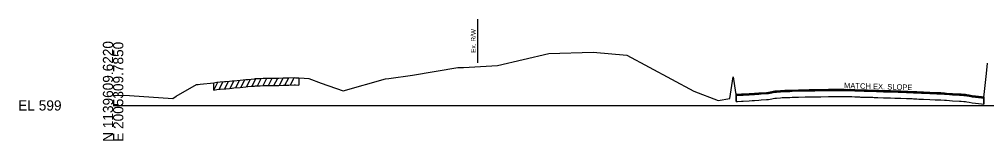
# Model space of a CAD drawing. Extents: x -201 to 2007062, y -213 to 1139737.
# Drawn here: x -25.7 to 239.3, y 490.3 to 523.7 of the extents above; entities that cross this region are included whole.
import ezdxf

# ---------------------------------------------------------------- set-up
doc = ezdxf.new("R2010")
doc.units = 0
for name, color, linetype in [('Default', 7, 'Continuous'), ('RD_GPK_XS_Cell', 7, 'Continuous'), ('RD_XS_ExGround', 7, 'Continuous'), ('RD_XS_ExPaveRet', 7, 'Continuous'), ('RD_XS_ExRW', 7, 'Continuous'), ('RD_XS_PaveOvlay', 7, 'Continuous'), ('RD_XS_TX_Slope', 7, 'Continuous')]:
    doc.layers.add(name, color=color, linetype=linetype)

msp = doc.modelspace()

# ---------------------------------------------------------------- linework, layer by layer
at = {"layer": 'RD_GPK_XS_Cell'}
msp.add_line((0, 500), (250, 500), dxfattribs=at)
at = {"layer": 'RD_XS_ExGround'}
msp.add_lwpolyline([(0, 502.8), (4.53, 502.75), (16.32, 501.89), (17.31, 502.56), (22.87, 505.74), (23.31, 505.78), (23.84, 505.83), (27.58, 506.23), (28.41, 506.37), (29.31, 506.45), (30.53, 506.57), (30.88, 506.6), (31.85, 506.69), (32.65, 506.76), (33.1, 506.8), (34.78, 506.95), (36.38, 507.11), (36.9, 507.16), (37.85, 507.25), (38.71, 507.33), (39.02, 507.36), (40.28, 507.41), (41.14, 507.45), (41.85, 507.46), (43.41, 507.47), (43.84, 507.48), (44.98, 507.51), (45.38, 507.52), (46.55, 507.55), (47.5, 507.57), (48.11, 507.59), (49.63, 507.64), (50, 507.62), (50.92, 507.61), (52.33, 507.52), (53.65, 507.39), (57.01, 506.14), (63.05, 503.99), (74.59, 507.28), (75.51, 507.42), (82.01, 508.34), (94.48, 510.4), (95.96, 510.44), (105.32, 510.97), (119.35, 514.25), (131.53, 514.68), (140.71, 513.81), (159.13, 503.88), (165.76, 501.33), (169, 501.89), (169.92, 507.82), (170.55, 503.57), (170.75, 503.12), (171.06, 503.11), (172.19, 503.15), (172.67, 503.16), (174.26, 503.26), (175.05, 503.31), (175.77, 503.37), (176.91, 503.48), (177.54, 503.5), (179.04, 503.59), (179.57, 503.64), (180.04, 503.75), (181.32, 503.98), (181.77, 504.02), (182.88, 504.11), (183.36, 504.14), (184.04, 504.18), (185.4, 504.2), (186.02, 504.23), (187.77, 504.3), (189.64, 504.33), (190.67, 504.34), (191.76, 504.35), (192.29, 504.36), (193.89, 504.4), (196.01, 504.45), (196.37, 504.47), (196.9, 504.47), (197.47, 504.47), (198.13, 504.47), (198.55, 504.46), (199.76, 504.45), (200.25, 504.44), (201.69, 504.42), (202.37, 504.41), (203.26, 504.39), (204.49, 504.32), (204.82, 504.31), (205.76, 504.28), (206.61, 504.26), (207.39, 504.24), (208.14, 504.23), (208.51, 504.21), (209.19, 504.18), (209.52, 504.17), (211.09, 504.11), (211.75, 504.1), (212.98, 504.08), (214.23, 504.04), (215.1, 504), (215.79, 503.97), (217.36, 503.91), (217.75, 503.9), (218.93, 503.86), (219.34, 503.83), (220.22, 503.79), (220.73, 503.76), (221.47, 503.74), (222.06, 503.71), (223.75, 503.65), (225.2, 503.58), (225.71, 503.56), (226.76, 503.51), (227.83, 503.45), (228.33, 503.41), (229.95, 503.28), (231.86, 503.17), (232.34, 503.15), (233.09, 503.1), (233.52, 503.07), (233.95, 503), (234.52, 502.88), (235.33, 502.71), (236.31, 502.61), (237.13, 502.51), (237.97, 502.43), (238.54, 502.39), (238.64, 503.03), (239.29, 508.81), (239.59, 511.58)], dxfattribs=at)
at = {"layer": 'RD_XS_ExPaveRet'}
for p, q in [((27.58, 504.23), (28.66, 506.39)), ((27.58, 504.23), (27.58, 506.23)), ((29.08, 504.43), (30.13, 506.53)), ((30.58, 504.57), (31.63, 506.67)), ((32.08, 504.71), (33.13, 506.81)), ((33.58, 504.85), (34.63, 506.94)), ((35.08, 504.98), (36.13, 507.08)), ((36.58, 505.13), (37.63, 507.23)), ((38.08, 505.27), (39.13, 507.36)), ((39.58, 505.38), (40.6, 507.42)), ((41.08, 505.44), (42.09, 507.46)), ((42.58, 505.47), (43.59, 507.48)), ((44.08, 505.49), (45.09, 507.51)), ((45.58, 505.52), (46.59, 507.55)), ((47.08, 505.56), (48.1, 507.59)), ((48.58, 505.61), (49.6, 507.64)), ((50.92, 507.61), (50.92, 505.61)), ((27.58, 504.23), (28.41, 504.37)), ((28.41, 504.37), (29.31, 504.45)), ((29.31, 504.45), (30.53, 504.57)), ((30.53, 504.57), (30.88, 504.6)), ((30.88, 504.6), (31.85, 504.69)), ((31.85, 504.69), (32.65, 504.76)), ((32.65, 504.76), (33.1, 504.8)), ((33.1, 504.8), (34.78, 504.95)), ((34.78, 504.95), (36.38, 505.11)), ((36.38, 505.11), (36.9, 505.16)), ((36.9, 505.16), (37.85, 505.25)), ((37.85, 505.25), (38.71, 505.33)), ((38.71, 505.33), (39.02, 505.36)), ((39.02, 505.36), (40.28, 505.41)), ((40.28, 505.41), (41.14, 505.45)), ((41.14, 505.45), (41.85, 505.46)), ((41.85, 505.46), (43.41, 505.47)), ((43.41, 505.47), (43.84, 505.48)), ((43.84, 505.48), (44.98, 505.51)), ((44.98, 505.51), (45.38, 505.52)), ((45.38, 505.52), (46.55, 505.55)), ((46.55, 505.55), (47.5, 505.57)), ((47.5, 505.57), (48.11, 505.59)), ((48.11, 505.59), (49.63, 505.64)), ((49.63, 505.64), (50, 505.62)), ((50, 505.62), (50.92, 505.61)), ((170.75, 501.12), (170.75, 503.12)), ((170.75, 502.79), (170.75, 501.12)), ((170.75, 501.12), (171.06, 501.11)), ((170.75, 501.12), (170.75, 501.12)), ((170.75, 501.12), (171.06, 501.11)), ((171.06, 501.11), (172.19, 501.15)), ((171.06, 501.11), (172.19, 501.15)), ((172.19, 501.15), (172.67, 501.16)), ((172.19, 501.15), (172.67, 501.16)), ((172.67, 501.16), (174.26, 501.26)), ((172.67, 501.16), (174.26, 501.26)), ((174.26, 501.26), (175.05, 501.31)), ((174.26, 501.26), (175.05, 501.31)), ((175.05, 501.31), (175.77, 501.37)), ((175.05, 501.31), (175.77, 501.37)), ((175.77, 501.37), (176.91, 501.48)), ((175.77, 501.37), (176.91, 501.48)), ((176.91, 501.48), (177.54, 501.5)), ((176.91, 501.48), (177.54, 501.5)), ((177.54, 501.5), (179.04, 501.59)), ((177.54, 501.5), (179.04, 501.59)), ((179.04, 501.59), (179.57, 501.64)), ((179.04, 501.59), (179.57, 501.64)), ((179.57, 501.64), (180.04, 501.75)), ((179.57, 501.64), (180.04, 501.75)), ((180.04, 501.75), (181.32, 501.98)), ((180.04, 501.75), (181.32, 501.98)), ((181.32, 501.98), (181.77, 502.02)), ((181.32, 501.98), (181.77, 502.02)), ((181.77, 502.02), (182.88, 502.11)), ((181.77, 502.02), (182.88, 502.11)), ((182.88, 502.11), (183.36, 502.14)), ((182.88, 502.11), (183.36, 502.14)), ((183.36, 502.14), (184.04, 502.18)), ((183.36, 502.14), (184.04, 502.18)), ((184.04, 502.18), (185.4, 502.2)), ((184.04, 502.18), (185.4, 502.2)), ((185.4, 502.2), (186.02, 502.23)), ((185.4, 502.2), (186.02, 502.23)), ((186.02, 502.23), (187.77, 502.3)), ((186.02, 502.23), (187.77, 502.3)), ((187.77, 502.3), (189.64, 502.33)), ((187.77, 502.3), (189.64, 502.33)), ((189.64, 502.33), (190.67, 502.34)), ((189.64, 502.33), (190.67, 502.34)), ((190.67, 502.34), (191.76, 502.35)), ((190.67, 502.34), (191.76, 502.35)), ((191.76, 502.35), (192.29, 502.36)), ((191.76, 502.35), (192.29, 502.36)), ((192.29, 502.36), (193.89, 502.4)), ((192.29, 502.36), (193.89, 502.4)), ((193.89, 502.4), (196.01, 502.45)), ((193.89, 502.4), (196.01, 502.45)), ((196.01, 502.45), (196.37, 502.47)), ((196.01, 502.45), (196.37, 502.47)), ((196.37, 502.47), (196.9, 502.47)), ((196.37, 502.47), (196.9, 502.47)), ((196.9, 502.47), (197.47, 502.47)), ((196.9, 502.47), (197.47, 502.47)), ((197.47, 502.47), (198.13, 502.47)), ((197.47, 502.47), (198.13, 502.47)), ((198.13, 502.47), (198.55, 502.46)), ((198.13, 502.47), (198.55, 502.46)), ((198.55, 502.46), (199.76, 502.45)), ((198.55, 502.46), (199.76, 502.45)), ((199.76, 502.45), (200.25, 502.44)), ((199.76, 502.45), (200.25, 502.44)), ((200.25, 502.44), (201.69, 502.42)), ((200.25, 502.44), (201.69, 502.42)), ((201.69, 502.42), (202.37, 502.41)), ((201.69, 502.42), (202.37, 502.41)), ((202.37, 502.41), (203.26, 502.39)), ((202.37, 502.41), (203.26, 502.39)), ((203.26, 502.39), (204.49, 502.32)), ((203.26, 502.39), (204.49, 502.32)), ((204.49, 502.32), (204.82, 502.31)), ((204.49, 502.32), (204.82, 502.31)), ((204.82, 502.31), (205.76, 502.28)), ((204.82, 502.31), (205.76, 502.28)), ((205.76, 502.28), (206.61, 502.26)), ((205.76, 502.28), (206.61, 502.26)), ((206.61, 502.26), (207.39, 502.24)), ((206.61, 502.26), (207.39, 502.24)), ((207.39, 502.24), (208.14, 502.23)), ((207.39, 502.24), (208.14, 502.23)), ((208.14, 502.23), (208.51, 502.21)), ((208.14, 502.23), (208.51, 502.21)), ((208.51, 502.21), (209.19, 502.18)), ((208.51, 502.21), (209.19, 502.18)), ((209.19, 502.18), (209.52, 502.17)), ((209.19, 502.18), (209.52, 502.17)), ((209.52, 502.17), (211.09, 502.11)), ((209.52, 502.17), (211.09, 502.11)), ((211.09, 502.11), (211.75, 502.1)), ((211.09, 502.11), (211.75, 502.1)), ((211.75, 502.1), (212.98, 502.08)), ((211.75, 502.1), (212.98, 502.08)), ((212.98, 502.08), (214.23, 502.04)), ((212.98, 502.08), (214.23, 502.04)), ((214.23, 502.04), (215.1, 502)), ((214.23, 502.04), (215.1, 502)), ((215.1, 502), (215.79, 501.97)), ((215.1, 502), (215.79, 501.97)), ((215.79, 501.97), (217.36, 501.91)), ((215.79, 501.97), (217.36, 501.91)), ((217.36, 501.91), (217.75, 501.9)), ((217.36, 501.91), (217.75, 501.9)), ((217.75, 501.9), (218.93, 501.86)), ((217.75, 501.9), (218.93, 501.86)), ((218.93, 501.86), (219.34, 501.83)), ((218.93, 501.86), (219.34, 501.83)), ((219.34, 501.83), (220.22, 501.79)), ((219.34, 501.83), (220.22, 501.79)), ((220.22, 501.79), (220.73, 501.76)), ((220.22, 501.79), (220.73, 501.76)), ((220.73, 501.76), (221.47, 501.74)), ((220.73, 501.76), (221.47, 501.74)), ((221.47, 501.74), (222.06, 501.71)), ((221.47, 501.74), (222.06, 501.71)), ((222.06, 501.71), (223.75, 501.65)), ((222.06, 501.71), (223.75, 501.65)), ((223.75, 501.65), (225.2, 501.58)), ((223.75, 501.65), (225.2, 501.58)), ((225.2, 501.58), (225.71, 501.56)), ((225.2, 501.58), (225.71, 501.56)), ((225.71, 501.56), (226.76, 501.51)), ((225.71, 501.56), (226.76, 501.51)), ((226.76, 501.51), (227.83, 501.45)), ((226.76, 501.51), (227.83, 501.45)), ((227.83, 501.45), (228.33, 501.41)), ((227.83, 501.45), (228.33, 501.41)), ((228.33, 501.41), (229.95, 501.28)), ((228.33, 501.41), (229.95, 501.28)), ((229.95, 501.28), (231.86, 501.17)), ((229.95, 501.28), (231.86, 501.17)), ((231.86, 501.17), (232.34, 501.15)), ((231.86, 501.17), (232.34, 501.15)), ((232.34, 501.15), (233.09, 501.1)), ((232.34, 501.15), (233.09, 501.1)), ((233.09, 501.1), (233.52, 501.07)), ((233.09, 501.1), (233.52, 501.07)), ((233.52, 501.07), (233.95, 501)), ((233.52, 501.07), (233.95, 501)), ((233.95, 501), (234.52, 500.88)), ((233.95, 501), (234.52, 500.88)), ((238.54, 502.39), (238.54, 500.39)), ((238.54, 500.39), (238.54, 502.06)), ((234.52, 500.88), (235.33, 500.71)), ((234.52, 500.88), (235.33, 500.71)), ((235.33, 500.71), (236.31, 500.61)), ((235.33, 500.71), (236.31, 500.61)), ((236.31, 500.61), (237.13, 500.51)), ((236.31, 500.61), (237.13, 500.51)), ((237.13, 500.51), (237.97, 500.43)), ((237.13, 500.51), (237.97, 500.43)), ((237.97, 500.43), (238.54, 500.39)), ((237.97, 500.43), (238.54, 500.39)), ((238.54, 500.39), (238.54, 500.39)), ((238.54, 500.39), (238.54, 500.39))]:
    msp.add_line(p, q, dxfattribs=at)
for points in [[(238.54, 502.06), (237.97, 502.1), (237.13, 502.18), (236.31, 502.28), (235.33, 502.37), (234.52, 502.55), (233.95, 502.67), (233.52, 502.74), (233.09, 502.77), (232.34, 502.82), (231.86, 502.83), (229.95, 502.95), (228.33, 503.08), (227.83, 503.11), (226.76, 503.18), (225.71, 503.23), (225.2, 503.25), (223.75, 503.32), (222.06, 503.38), (221.47, 503.41), (220.73, 503.43), (220.22, 503.46), (219.34, 503.5), (218.93, 503.52), (217.75, 503.57), (217.36, 503.58), (215.79, 503.64), (215.1, 503.67), (214.23, 503.71), (212.98, 503.75), (211.75, 503.77), (211.09, 503.78), (209.52, 503.84), (209.19, 503.85), (208.51, 503.88), (208.14, 503.89), (207.39, 503.91), (206.61, 503.93), (205.76, 503.95), (204.82, 503.97), (204.49, 503.99), (203.26, 504.05), (202.37, 504.08), (201.69, 504.09), (200.25, 504.11), (199.76, 504.12), (198.55, 504.13), (198.13, 504.14), (197.47, 504.14), (196.9, 504.14), (196.37, 504.14), (196.01, 504.11), (193.89, 504.07), (192.29, 504.02), (191.76, 504.01), (190.67, 504.01), (189.64, 503.99), (187.77, 503.97), (186.02, 503.89), (185.4, 503.86), (184.04, 503.85), (183.36, 503.81), (182.88, 503.77), (181.77, 503.69), (181.32, 503.65), (180.04, 503.41), (179.57, 503.31), (179.04, 503.26), (177.54, 503.17), (176.91, 503.14), (175.77, 503.04), (175.05, 502.98), (174.26, 502.93), (172.67, 502.83), (172.19, 502.82), (171.06, 502.78), (170.75, 502.79)], [(238.54, 502.06), (238.54, 502.06)]]:
    msp.add_lwpolyline(points, dxfattribs=at)
at = {"layer": 'RD_XS_ExRW'}
msp.add_line((99.85, 523.67), (99.85, 511.67), dxfattribs=at)
at = {"layer": 'RD_XS_PaveOvlay'}
for points in [[(170.75, 503.12), (170.75, 503.12), (171.06, 503.11), (172.19, 503.15), (172.67, 503.16), (174.26, 503.26), (175.05, 503.31), (175.77, 503.37), (176.91, 503.48), (177.54, 503.5), (179.04, 503.59), (179.57, 503.64), (180.04, 503.75), (181.32, 503.98), (181.77, 504.02), (182.88, 504.11), (183.36, 504.14), (184.04, 504.18), (185.4, 504.2), (186.02, 504.23), (187.77, 504.3), (189.64, 504.33), (190.67, 504.34), (191.76, 504.35), (192.29, 504.36), (193.89, 504.4), (196.01, 504.45), (196.37, 504.47), (196.9, 504.47), (197.47, 504.47), (198.13, 504.47), (198.55, 504.46), (199.76, 504.45), (200.25, 504.44), (201.69, 504.42), (202.37, 504.41), (203.26, 504.39), (204.49, 504.32), (204.82, 504.31), (205.76, 504.28), (206.61, 504.26), (207.39, 504.24), (208.14, 504.23), (208.51, 504.21), (209.19, 504.18), (209.52, 504.17), (211.09, 504.11), (211.75, 504.1), (212.98, 504.08), (214.23, 504.04), (215.1, 504), (215.79, 503.97), (217.36, 503.91), (217.75, 503.9), (218.93, 503.86), (219.34, 503.83), (220.22, 503.79), (220.73, 503.76), (221.47, 503.74), (222.06, 503.71), (223.75, 503.65), (225.2, 503.58), (225.71, 503.56), (226.76, 503.51), (227.83, 503.45), (228.33, 503.41), (229.95, 503.28), (231.86, 503.17), (232.34, 503.15), (233.09, 503.1), (233.52, 503.07), (233.95, 503), (234.52, 502.88), (235.33, 502.71), (236.31, 502.61), (237.13, 502.51), (237.97, 502.43), (238.54, 502.39), (238.54, 502.39)], [(170.75, 502.79), (170.75, 502.79), (171.06, 502.78), (172.19, 502.82), (172.67, 502.83), (174.26, 502.93), (175.05, 502.98), (175.77, 503.04), (176.91, 503.14), (177.54, 503.17), (179.04, 503.26), (179.57, 503.31), (180.04, 503.41), (181.32, 503.65), (181.77, 503.69), (182.88, 503.77), (183.36, 503.81), (184.04, 503.85), (185.4, 503.86), (186.02, 503.89), (187.77, 503.97), (189.64, 503.99), (190.67, 504.01), (191.76, 504.01), (192.29, 504.02), (193.89, 504.07), (196.01, 504.11), (196.37, 504.14), (196.9, 504.14), (197.47, 504.14), (198.13, 504.14), (198.55, 504.13), (199.76, 504.12), (200.25, 504.11), (201.69, 504.09), (202.37, 504.08), (203.26, 504.05), (204.49, 503.99), (204.82, 503.97), (205.76, 503.95), (206.61, 503.93), (207.39, 503.91), (208.14, 503.89), (208.51, 503.88), (209.19, 503.85), (209.52, 503.84), (211.09, 503.78), (211.75, 503.77), (212.98, 503.75), (214.23, 503.71), (215.1, 503.67), (215.79, 503.64), (217.36, 503.58), (217.75, 503.57), (218.93, 503.52), (219.34, 503.5), (220.22, 503.46), (220.73, 503.43), (221.47, 503.41), (222.06, 503.38), (223.75, 503.32), (225.2, 503.25), (225.71, 503.23), (226.76, 503.18), (227.83, 503.11), (228.33, 503.08), (229.95, 502.95), (231.86, 502.83), (232.34, 502.82), (233.09, 502.77), (233.52, 502.74), (233.95, 502.67), (234.52, 502.55), (235.33, 502.37), (236.31, 502.28), (237.13, 502.18), (237.97, 502.1), (238.54, 502.06), (238.54, 502.06)]]:
    msp.add_lwpolyline(points, dxfattribs=at)

# ---------------------------------------------------------------- texts
at = {"layer": 'Default'}
msp.add_text('-', height=0.0001, dxfattribs=at).set_placement((0, 500))
at = {"layer": 'RD_GPK_XS_Cell'}
for s, p in [('N 1139609.6220', (0, 490)), ('E 2005309.7850', (2.8, 490))]:
    msp.add_text(s, height=2.8, rotation=90, dxfattribs=at).set_placement(p)
msp.add_text('EL 599', height=2.8, dxfattribs=at).set_placement((-26, 498.6))
at = {"layer": 'RD_XS_ExRW'}
msp.add_text('Ex. R/W ', height=1.3, rotation=90, dxfattribs=at).set_placement((99.35, 514.43))
at = {"layer": 'RD_XS_TX_Slope'}
msp.add_text('MATCH EX. SLOPE', height=1.5, rotation=358.3671, dxfattribs=at).set_placement((200.25, 504.73))

doc.saveas('drawing.dxf')
